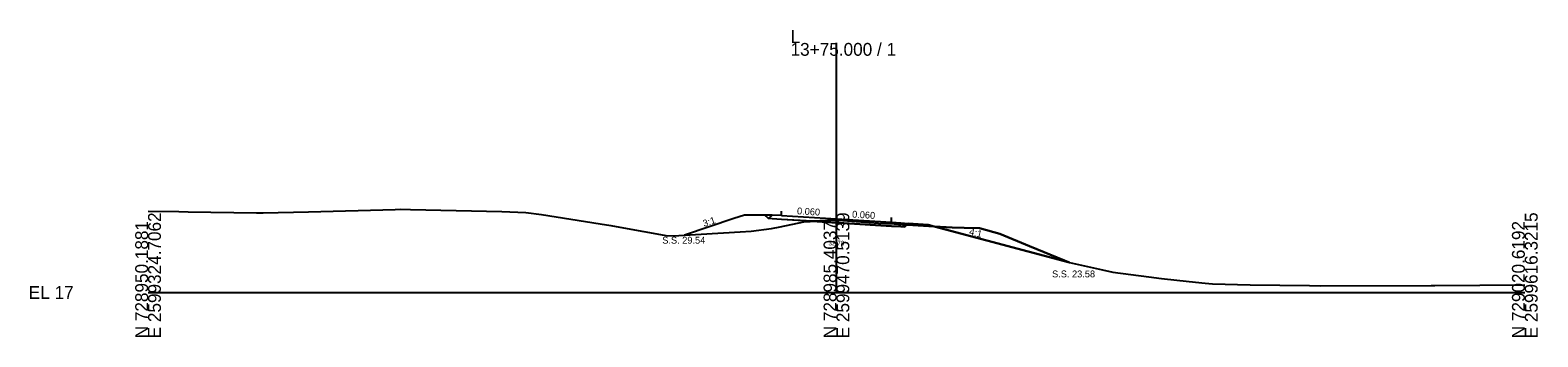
# Model space of a CAD drawing. Extents: x -26 to 3303, y -10 to 9555.
# Drawn here: x -25.7 to 302.8, y 7490.3 to 7557.3 of the extents above; entities that cross this region are included whole.
import ezdxf

# ---------------------------------------------------------------- set-up
doc = ezdxf.new("R2010")
doc.units = 0
for name, color, linetype in [('Exist Cross Section Cell', 7, 'Continuous'), ('Exist XS Center Line Elevation Label', 7, 'Continuous'), ('Exist XS Ground Line', 7, 'Continuous'), ('Prop XS Ditch Slope Text', 7, 'Continuous'), ('Prop XS Dump Level', 7, 'Continuous'), ('Prop XS Earthwork Shape', 7, 'Continuous'), ('Prop XS EOT Tick Mark', 7, 'Continuous'), ('Prop XS Finish Grade', 7, 'Continuous'), ('Prop XS Finish Grade Earthwork', 7, 'Continuous'), ('Prop XS Finish Grade Paved Shoulder', 7, 'Continuous'), ('Prop XS Finish Grade Pavement', 7, 'Continuous'), ('Prop XS Pvmt Edge Slope', 7, 'Continuous'), ('Prop XS SE Text', 7, 'Continuous'), ('Prop XS Side Slope Text', 7, 'Continuous'), ('Prop XS SS Elevation Text', 7, 'Continuous'), ('Prop XS Subgrade Earthwork', 7, 'Continuous')]:
    doc.layers.add(name, color=color, linetype=linetype)

msp = doc.modelspace()

# ---------------------------------------------------------------- linework, layer by layer
at = {"layer": 'Exist Cross Section Cell'}
for p, q in [((150, 7500), (150, 7554.48)), ((0, 7500), (150, 7500)), ((150, 7500), (300, 7500))]:
    msp.add_line(p, q, dxfattribs=at)
at = {"layer": 'Exist XS Ground Line'}
msp.add_lwpolyline([(0, 7517.75), (6.68, 7517.65), (8.72, 7517.59), (23.62, 7517.41), (25.09, 7517.4), (34.96, 7517.64), (53.85, 7518.13), (55.09, 7518.16), (57.16, 7518.1), (77.09, 7517.66), (82.31, 7517.43), (85.7, 7517.02), (98.48, 7515.02), (100.87, 7514.66), (102.81, 7514.29), (113.29, 7512.4), (115.65, 7512.47), (129.05, 7513.23), (131.42, 7513.36), (135.88, 7513.98), (137.76, 7514.32), (142.88, 7515.46), (149.63, 7515.77), (150, 7515.78), (150.43, 7515.8), (159.17, 7515.16), (162.56, 7514.96), (166.62, 7514.68), (175.24, 7514.16), (177.84, 7514.14), (181.21, 7514.08), (185.63, 7512.78), (192.04, 7510.14), (199.72, 7506.99), (200.75, 7506.58), (207.94, 7504.94), (210.26, 7504.41), (218.04, 7503.42), (220.82, 7503.08), (226.88, 7502.4), (230.37, 7502.01), (231.98, 7501.9), (240.12, 7501.7), (253.08, 7501.5), (255.41, 7501.48), (279.63, 7501.55), (280.4, 7501.56), (300, 7501.64)], dxfattribs=at)
at = {"layer": 'Prop XS Dump Level'}
for p, q in [((138, 7516.78), (150, 7516.06)), ((150, 7516.06), (162, 7515.34))]:
    msp.add_line(p, q, dxfattribs=at)
at = {"layer": 'Prop XS Earthwork Shape'}
for points in [[(116.91, 7512.54), (129.05, 7513.23), (131.42, 7513.36), (135.88, 7513.98), (137.76, 7514.32), (142.88, 7515.46), (144.79, 7515.54), (138, 7515.95), (136, 7516.07), (135.21, 7516.12), (134.43, 7516.9), (130, 7516.9), (127.64, 7516.12)], [(116.91, 7512.54), (129.05, 7513.23), (131.42, 7513.36), (135.88, 7513.98), (137.76, 7514.32), (142.88, 7515.46), (144.79, 7515.54), (138, 7515.95), (136, 7516.07), (135.21, 7516.12), (134.43, 7516.9), (130, 7516.9), (127.64, 7516.12)], [(150.43, 7515.2), (150.43, 7515.8), (150, 7515.78), (149.63, 7515.77), (144.79, 7515.54), (150, 7515.23)], [(150.43, 7515.2), (150.43, 7515.8), (150, 7515.78), (149.63, 7515.77), (144.79, 7515.54), (150, 7515.23)], [(150.43, 7515.2), (150.43, 7515.8), (159.17, 7515.16), (162.56, 7514.96), (165.32, 7514.77), (164.89, 7514.34), (164, 7514.39), (162, 7514.51)], [(150.43, 7515.2), (150.43, 7515.8), (159.17, 7515.16), (162.56, 7514.96), (165.32, 7514.77), (164.89, 7514.34), (164, 7514.39), (162, 7514.51)], [(165.32, 7514.77), (166.62, 7514.68), (171.3, 7514.4), (170, 7514.74), (165.64, 7515.09)], [(165.64, 7515.09), (170, 7514.74), (171.3, 7514.4), (166.62, 7514.68), (165.32, 7514.77)], [(171.3, 7514.4), (175.24, 7514.16), (177.84, 7514.14), (181.21, 7514.08), (185.63, 7512.78), (192.04, 7510.14), (199.72, 7506.99), (200.75, 7506.58), (173.75, 7513.75)], [(171.3, 7514.4), (173.75, 7513.75), (200.75, 7506.58), (199.72, 7506.99), (192.04, 7510.14), (185.63, 7512.78), (181.21, 7514.08), (177.84, 7514.14), (175.24, 7514.16)]]:
    msp.add_lwpolyline(points, close=True, dxfattribs=at)
at = {"layer": 'Prop XS EOT Tick Mark'}
for p, q in [((138, 7516.78), (138, 7517.78)), ((162, 7515.34), (162, 7516.34))]:
    msp.add_line(p, q, dxfattribs=at)
at = {"layer": 'Prop XS Finish Grade'}
for p, q in [((136, 7516.9), (134.43, 7516.9)), ((164, 7515.22), (165.64, 7515.09))]:
    msp.add_line(p, q, dxfattribs=at)
at = {"layer": 'Prop XS Finish Grade Earthwork'}
for p, q in [((130, 7516.9), (127.64, 7516.12)), ((134.43, 7516.9), (130, 7516.9)), ((127.64, 7516.12), (116.91, 7512.54)), ((165.64, 7515.09), (170, 7514.74)), ((170, 7514.74), (173.75, 7513.75)), ((173.75, 7513.75), (200.75, 7506.58))]:
    msp.add_line(p, q, dxfattribs=at)
at = {"layer": 'Prop XS Finish Grade Paved Shoulder'}
for p, q in [((138, 7516.78), (136, 7516.9)), ((162, 7515.34), (164, 7515.22))]:
    msp.add_line(p, q, dxfattribs=at)
at = {"layer": 'Prop XS Finish Grade Pavement'}
for p, q in [((138, 7516.78), (150, 7516.06)), ((150, 7516.06), (162, 7515.34))]:
    msp.add_line(p, q, dxfattribs=at)
at = {"layer": 'Prop XS Pvmt Edge Slope'}
for p, q in [((135.21, 7516.12), (134.43, 7516.9)), ((136, 7516.9), (135.21, 7516.12)), ((164, 7515.22), (164.89, 7514.34)), ((164.89, 7514.34), (165.64, 7515.09))]:
    msp.add_line(p, q, dxfattribs=at)
at = {"layer": 'Prop XS Subgrade Earthwork'}
for p, q in [((135.21, 7516.12), (134.43, 7516.9)), ((136, 7516.07), (135.21, 7516.12)), ((138, 7515.95), (136, 7516.07)), ((150, 7515.23), (138, 7515.95)), ((150.43, 7515.2), (150, 7515.23)), ((150.43, 7515.2), (150.43, 7515.8)), ((150.43, 7515.2), (150.43, 7515.8)), ((150.43, 7515.2), (162, 7514.51)), ((162, 7514.51), (164, 7514.39)), ((164, 7514.39), (164.89, 7514.34)), ((164.89, 7514.34), (165.64, 7515.09))]:
    msp.add_line(p, q, dxfattribs=at)

# ---------------------------------------------------------------- texts
at = {"layer": 'Exist Cross Section Cell'}
for s, p in [('L', (140, 7554.48)), ('13+75.000 / 1', (140, 7551.68)), ('EL 17', (-26, 7498.6))]:
    msp.add_text(s, height=2.8, dxfattribs=at).set_placement(p)
for s, p in [('E 2599324.7062', (2.8, 7490)), ('E 2599470.5139', (152.8, 7490)), ('E 2599616.3215', (302.8, 7490)), ('N 728950.1881', (0, 7490)), ('N 728985.4037', (150, 7490)), ('N 729020.6192', (300, 7490))]:
    msp.add_text(s, height=2.8, rotation=90, dxfattribs=at).set_placement(p)
at = {"layer": 'Exist XS Center Line Elevation Label'}
msp.add_text('32.78', height=1, dxfattribs=at).set_placement((148.26, 7510.28))
at = {"layer": 'Prop XS Ditch Slope Text'}
msp.add_text('4:1', height=1.5, rotation=345.9638, dxfattribs=at).set_placement((178.82, 7512.64))
at = {"layer": 'Prop XS Dump Level'}
for s, height, p in [('Case1', 0.04, (130, 7516.86)), ('Eop', 0.3, (150.43, 7515.5)), ('Eop', 0.3, (150.43, 7515.5))]:
    msp.add_text(s, height=height, dxfattribs=at).set_placement(p)
at = {"layer": 'Prop XS SE Text'}
for p in [(141.38, 7517.08), (153.38, 7516.36)]:
    msp.add_text('0.060', height=1.5, rotation=356.5664, dxfattribs=at).set_placement(p)
at = {"layer": 'Prop XS Side Slope Text'}
msp.add_text('3:1', height=1.5, rotation=18.4349, dxfattribs=at).set_placement((121.16, 7514.29))
at = {"layer": 'Prop XS SS Elevation Text'}
for s, p in [('S.S. 29.54', (112.05, 7510.66)), ('S.S. 23.58', (196.99, 7503.3))]:
    msp.add_text(s, height=1.5, dxfattribs=at).set_placement(p)

doc.saveas('drawing.dxf')
